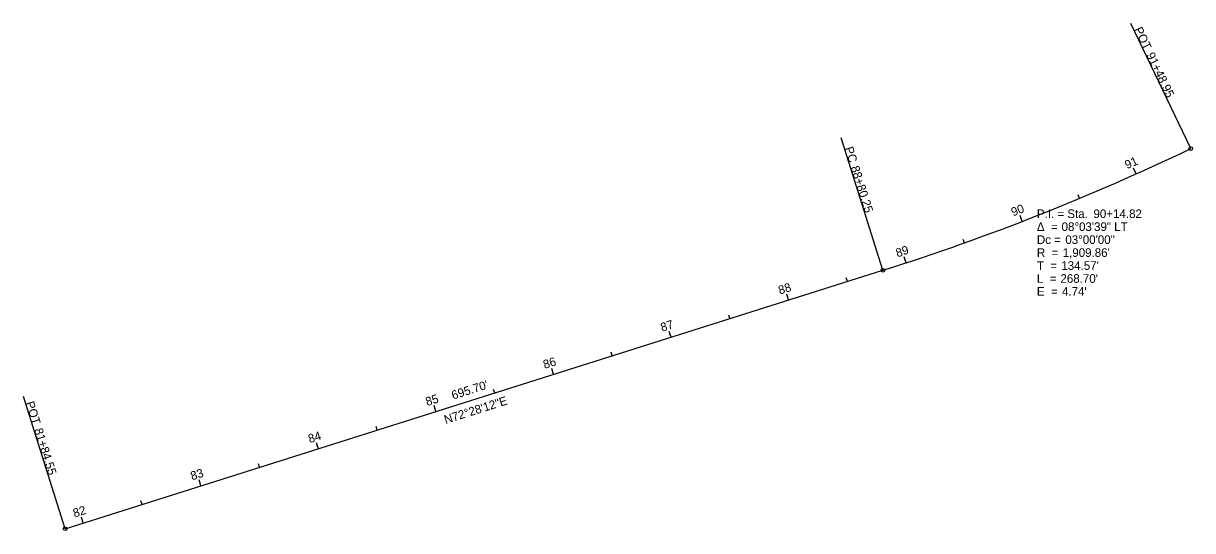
# Model space of a CAD drawing. Extents: x 2193326 to 2194275, y 660638 to 661049.
import ezdxf

# ---------------------------------------------------------------- set-up
doc = ezdxf.new("R2010")
doc.units = 0
for name, color, linetype in [('Default', 7, 'Continuous'), ('GE_X_Alignment', 7, 'Continuous'), ('GE_X_Alignment_1000_Curve_Data', 7, 'Continuous'), ('GE_X_Alignment_1000_Stations', 7, 'Continuous'), ('GE_X_Alignment_100_Curve_Data', 7, 'Continuous'), ('GE_X_Alignment_100_Stations', 7, 'Continuous'), ('GE_X_Alignment_500_Curve_Data', 7, 'Continuous'), ('GE_X_Alignment_500_Stations', 7, 'Continuous')]:
    doc.layers.add(name, color=color, linetype=linetype)

msp = doc.modelspace()

# ---------------------------------------------------------------- linework, layer by layer
at = {"layer": 'Default'}
for centre in [(2194273.26, 660947.52), (2194273.26, 660947.52), (2194273.26, 660947.52), (2194228.85, 660926.95), (2194148.42, 660898.19), (2194148.42, 660898.19), (2194148.42, 660898.19), (2194136.55, 660888.49), (2194136.55, 660888.49), (2194136.55, 660888.49), (2194023.57, 660848.86), (2194023.57, 660848.86), (2194023.57, 660848.86), (2194042.37, 660854.91), (2193947.05, 660824.69), (2193851.69, 660794.57), (2193756.34, 660764.45), (2193691.87, 660744.09), (2193691.87, 660744.09), (2193691.87, 660744.09), (2193691.87, 660744.09), (2193691.87, 660744.09), (2193691.87, 660744.09), (2193660.98, 660734.33), (2193660.98, 660734.33), (2193565.62, 660704.21), (2193470.27, 660674.09), (2193360.17, 660639.31), (2193360.17, 660639.31), (2193360.17, 660639.31), (2193374.91, 660643.97)]:
    msp.add_circle(centre, 0.0000833, dxfattribs=at)
at = {"layer": 'GE_X_Alignment'}
msp.add_line((2193360.17, 660639.31), (2194023.57, 660848.86), dxfattribs=at)
msp.add_arc((2193448.31, 662670.03), 1909.86, 287.5299, 295.59078, dxfattribs=at)
at = {"layer": 'GE_X_Alignment_1000_Stations'}
for p, q in [((2194273.26, 660947.52), (2194224.67, 661048.98)), ((2194023.57, 660848.86), (2193989.69, 660956.14)), ((2194136.55, 660888.49), (2194134.75, 660893.15)), ((2193360.17, 660639.31), (2193326.29, 660746.59)), ((2193660.98, 660734.33), (2193660.08, 660737.19))]:
    msp.add_line(p, q, dxfattribs=at)
for centre in [(2194273.26, 660947.52), (2194023.57, 660848.86), (2193360.17, 660639.31)]:
    msp.add_circle(centre, 1.5, dxfattribs=at)
at = {"layer": 'GE_X_Alignment_100_Stations'}
for p, q in [((2194273.26, 660947.52), (2194224.67, 661048.98)), ((2194023.57, 660848.86), (2193989.69, 660956.14)), ((2194228.85, 660926.95), (2194226.81, 660931.51)), ((2194182.95, 660907.11), (2194181.8, 660909.88)), ((2194136.55, 660888.49), (2194134.75, 660893.15)), ((2194089.68, 660871.08), (2194088.68, 660873.91)), ((2194042.37, 660854.91), (2194040.82, 660859.66)), ((2193994.73, 660839.75), (2193993.82, 660842.61)), ((2193947.05, 660824.69), (2193945.54, 660829.46)), ((2193899.37, 660809.63), (2193898.47, 660812.49)), ((2193851.69, 660794.57), (2193850.19, 660799.34)), ((2193804.01, 660779.51), (2193803.11, 660782.37)), ((2193756.34, 660764.45), (2193754.83, 660769.22)), ((2193360.17, 660639.31), (2193326.29, 660746.59)), ((2193708.66, 660749.39), (2193707.75, 660752.25)), ((2193660.98, 660734.33), (2193659.47, 660739.1)), ((2193613.3, 660719.27), (2193612.4, 660722.13)), ((2193565.62, 660704.21), (2193564.12, 660708.98)), ((2193517.95, 660689.15), (2193517.04, 660692.01)), ((2193470.27, 660674.09), (2193468.76, 660678.86)), ((2193422.59, 660659.03), (2193421.69, 660661.89)), ((2193374.91, 660643.97), (2193373.41, 660648.74))]:
    msp.add_line(p, q, dxfattribs=at)
for centre in [(2194273.26, 660947.52), (2194023.57, 660848.86), (2193360.17, 660639.31)]:
    msp.add_circle(centre, 1.5, dxfattribs=at)
at = {"layer": 'GE_X_Alignment_500_Stations'}
for p, q in [((2194273.26, 660947.52), (2194224.67, 661048.98)), ((2194023.57, 660848.86), (2193989.69, 660956.14)), ((2194228.85, 660926.95), (2194227.62, 660929.69)), ((2194136.55, 660888.49), (2194134.75, 660893.15)), ((2194042.37, 660854.91), (2194041.44, 660857.76)), ((2193947.05, 660824.69), (2193946.14, 660827.55)), ((2193851.69, 660794.57), (2193850.79, 660797.43)), ((2193756.34, 660764.45), (2193755.43, 660767.31)), ((2193360.17, 660639.31), (2193326.29, 660746.59)), ((2193660.98, 660734.33), (2193659.47, 660739.1)), ((2193565.62, 660704.21), (2193564.72, 660707.07)), ((2193470.27, 660674.09), (2193469.36, 660676.95)), ((2193374.91, 660643.97), (2193374.01, 660646.83))]:
    msp.add_line(p, q, dxfattribs=at)
for centre in [(2194273.26, 660947.52), (2194023.57, 660848.86), (2193360.17, 660639.31)]:
    msp.add_circle(centre, 1.5, dxfattribs=at)

# ---------------------------------------------------------------- texts
at = {"layer": 'GE_X_Alignment_1000_Curve_Data'}
for s, p in [('P.I. = Sta. ', (2194148.42, 660891.19)), ('90+14.82', (2194194.34, 660891.19)), ('Δ  = ', (2194148.42, 660880.69)), ('08°03\'39" LT', (2194168.47, 660880.69)), ('Dc = ', (2194148.42, 660870.19)), ('03°00\'00"', (2194171.51, 660870.19)), ('R  = ', (2194148.42, 660859.69)), ("1,909.86'", (2194169.34, 660859.69)), ('T  = ', (2194148.42, 660849.19)), ("134.57'", (2194168.25, 660849.19)), ('L  = ', (2194148.42, 660838.69)), ("268.70'", (2194167.53, 660838.69)), ('E  = ', (2194148.42, 660828.19)), ("4.74'", (2194168.8, 660828.19))]:
    msp.add_text(s, height=7, dxfattribs=at).set_placement(p)
at = {"layer": 'GE_X_Alignment_1000_Stations'}
for s, rotation, p in [('POT', 295.59078, (2194227.14, 661044.09)), ('91+48.95', 295.59078, (2194237, 661023.5)), ('PC', 287.5299, (2193992.43, 660947.83)), ('88+80.25', 287.5299, (2193997.34, 660932.29)), ('90', 21.1224, (2194129.15, 660892.45)), ("695.70'", 17.52992, (2193674.91, 660743.97)), ('N72°28\'12"E', 17.52992, (2193668.83, 660724.23)), ('POT', 287.52992, (2193328.05, 660741.39)), ('81+84.55', 287.52992, (2193334.93, 660719.63))]:
    msp.add_text(s, height=7, rotation=rotation, dxfattribs=at).set_placement(p)
at = {"layer": 'GE_X_Alignment_100_Curve_Data'}
for s, p in [('P.I. = Sta. ', (2194148.42, 660891.19)), ('90+14.82', (2194194.34, 660891.19)), ('Δ  = ', (2194148.42, 660880.69)), ('08°03\'39" LT', (2194168.47, 660880.69)), ('Dc = ', (2194148.42, 660870.19)), ('03°00\'00"', (2194171.51, 660870.19)), ('R  = ', (2194148.42, 660859.69)), ("1,909.86'", (2194169.34, 660859.69)), ('T  = ', (2194148.42, 660849.19)), ("134.57'", (2194168.25, 660849.19)), ('L  = ', (2194148.42, 660838.69)), ("268.70'", (2194167.53, 660838.69)), ('E  = ', (2194148.42, 660828.19)), ("4.74'", (2194168.8, 660828.19))]:
    msp.add_text(s, height=7, dxfattribs=at).set_placement(p)
at = {"layer": 'GE_X_Alignment_100_Stations'}
for s, rotation, p in [('POT', 295.59078, (2194227.14, 661044.09)), ('91+48.95', 295.59078, (2194237, 661023.5)), ('PC', 287.5299, (2193992.43, 660947.83)), ('88+80.25', 287.5299, (2193997.34, 660932.29)), ('91', 24.1224, (2194221.63, 660930.69)), ('90', 21.1224, (2194129.15, 660892.45)), ('89', 18.1224, (2194035.25, 660859.28)), ('88', 17.52992, (2193939.91, 660829.11)), ('87', 17.52992, (2193844.41, 660798.95)), ('86', 17.52992, (2193749.18, 660768.87)), ("695.70'", 17.52992, (2193674.91, 660743.97)), ('85', 17.52992, (2193653.8, 660738.74)), ('N72°28\'12"E', 17.52992, (2193668.83, 660724.23)), ('POT', 287.52992, (2193328.05, 660741.39)), ('81+84.55', 287.52992, (2193334.93, 660719.63)), ('84', 17.52992, (2193558.58, 660708.66)), ('83', 17.52992, (2193463.16, 660678.52)), ('82', 17.52992, (2193367.78, 660648.39))]:
    msp.add_text(s, height=7, rotation=rotation, dxfattribs=at).set_placement(p)
at = {"layer": 'GE_X_Alignment_500_Curve_Data'}
for s, p in [('P.I. = Sta. ', (2194148.42, 660891.19)), ('90+14.82', (2194194.34, 660891.19)), ('Δ  = ', (2194148.42, 660880.69)), ('08°03\'39" LT', (2194168.47, 660880.69)), ('Dc = ', (2194148.42, 660870.19)), ('03°00\'00"', (2194171.51, 660870.19)), ('R  = ', (2194148.42, 660859.69)), ("1,909.86'", (2194169.34, 660859.69)), ('T  = ', (2194148.42, 660849.19)), ("134.57'", (2194168.25, 660849.19)), ('L  = ', (2194148.42, 660838.69)), ("268.70'", (2194167.53, 660838.69)), ('E  = ', (2194148.42, 660828.19)), ("4.74'", (2194168.8, 660828.19))]:
    msp.add_text(s, height=7, dxfattribs=at).set_placement(p)
at = {"layer": 'GE_X_Alignment_500_Stations'}
for s, rotation, p in [('POT', 295.59078, (2194227.14, 661044.09)), ('91+48.95', 295.59078, (2194237, 661023.5)), ('PC', 287.5299, (2193992.43, 660947.83)), ('88+80.25', 287.5299, (2193997.34, 660932.29)), ('90', 21.1224, (2194129.15, 660892.45)), ("695.70'", 17.52992, (2193674.91, 660743.97)), ('85', 17.52992, (2193653.8, 660738.74)), ('N72°28\'12"E', 17.52992, (2193668.83, 660724.23)), ('POT', 287.52992, (2193328.05, 660741.39)), ('81+84.55', 287.52992, (2193334.93, 660719.63))]:
    msp.add_text(s, height=7, rotation=rotation, dxfattribs=at).set_placement(p)

doc.saveas('drawing.dxf')
